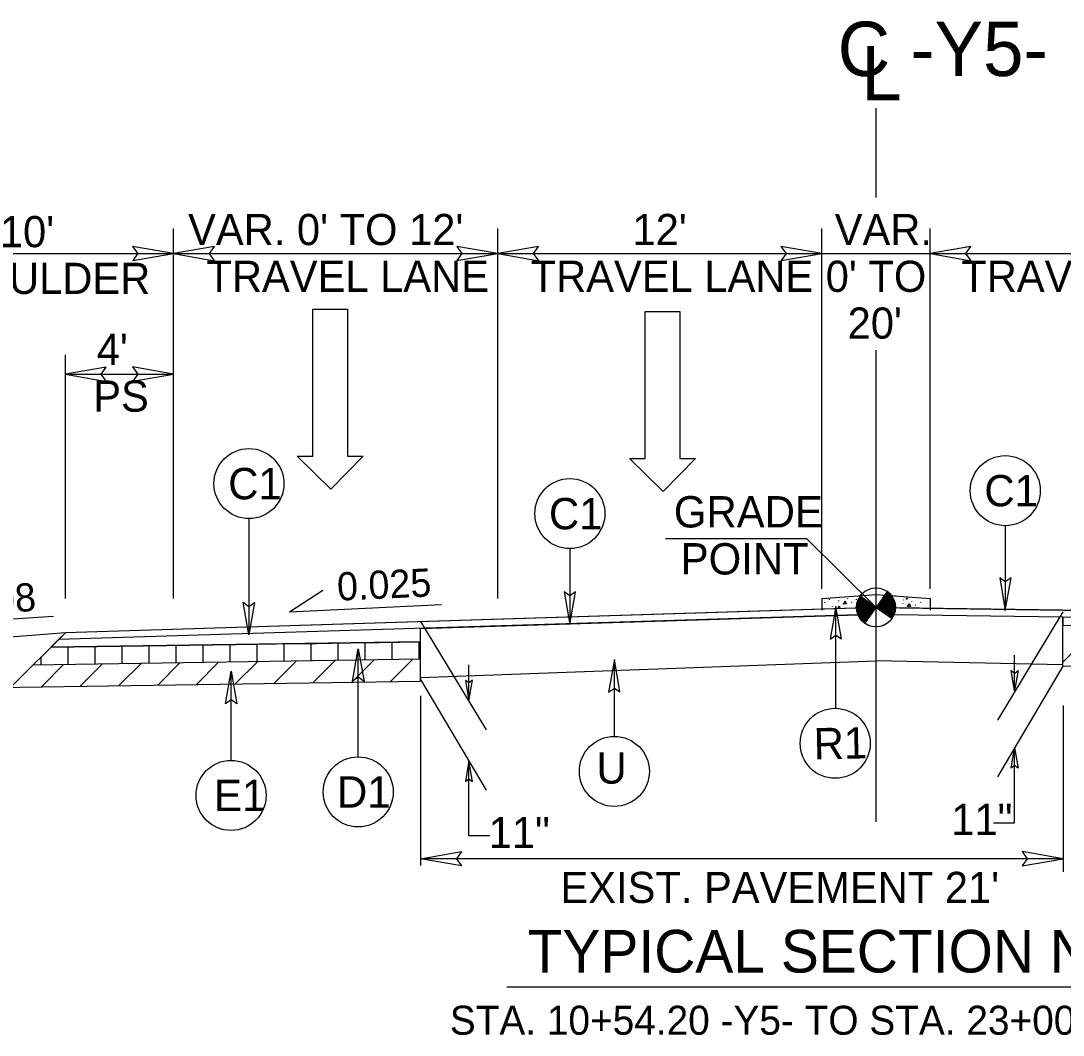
# Model space of a CAD drawing. Extents: x 2176156 to 2177167, y 76401 to 76644.
# Drawn here: x 2176264.04 to 2176302.62, y 76503.74 to 76541.28 of the extents above; entities that cross this region are included whole.
import ezdxf

# ---------------------------------------------------------------- set-up
doc = ezdxf.new("R2010")
doc.units = 0
for name, color, linetype in [('Exist Building', 7, 'Continuous'), ('Exist Building Metal Canopy', 7, 'Continuous'), ('Exist Roads Change in Surface', 7, 'Continuous'), ('Exist Roads Curbs', 7, 'Continuous'), ('Exist Roads EOP Other', 7, 'Continuous'), ('Exist Roads Soil', 7, 'Continuous'), ('Exist Structure Minor Culvert Topo', 7, 'Continuous'), ('Exist Structure Minor Drop Inlet', 7, 'Continuous'), ('Exist Utilities Other Pole CELL', 7, 'Continuous'), ('Exist Vegetation Woods Line', 7, 'Continuous'), ('Model Boundary Lines Text', 7, 'Continuous'), ('Old_Level_1', 7, 'Continuous'), ('Old_Level_3', 7, 'Continuous'), ('Prop North Arrow NAD83 for Plan Sheets CELL', 7, 'Continuous'), ('Sheet Plan CELL', 7, 'Continuous')]:
    doc.layers.add(name, color=color, linetype=linetype)

msp = doc.modelspace()

# ---------------------------------------------------------------- linework, layer by layer
at = {"layer": 'Exist Building'}
for p, q in [((2176302.609, 76517.393), (2176302.609, 76519.216)), ((2176278.832, 76516.842), (2176278.832, 76518.793)), ((2176342.792, 76516.795), (2176302.609, 76517.393)), ((2176249.154, 76516.4), (2176278.832, 76516.842))]:
    msp.add_line(p, q, dxfattribs=at)
at = {"layer": 'Exist Roads Change in Surface'}
for p, q in [((2176294.327, 76519.95), (2176294.335, 76519.938)), ((2176294.625, 76519.895), (2176294.634, 76519.881)), ((2176295.689, 76519.569), (2176295.097, 76519.98)), ((2176296.101, 76520.16), (2176295.689, 76519.569)), ((2176296.404, 76519.988), (2176296.406, 76519.998)), ((2176296.425, 76519.997), (2176296.406, 76519.988)), ((2176293.783, 76519.754), (2176293.792, 76519.774)), ((2176293.963, 76519.851), (2176293.972, 76519.871)), ((2176294.061, 76519.612), (2176294.07, 76519.598)), ((2176294.309, 76519.805), (2176294.318, 76519.825)), ((2176294.783, 76519.754), (2176294.792, 76519.774)), ((2176294.963, 76519.851), (2176294.972, 76519.871)), ((2176295.277, 76518.977), (2176295.689, 76519.569)), ((2176296.282, 76519.158), (2176295.689, 76519.569)), ((2176295.689, 76519.569), (2176296.282, 76519.158)), ((2176296.682, 76519.707), (2176296.691, 76519.727)), ((2176296.699, 76519.853), (2176296.708, 76519.84)), ((2176296.998, 76519.796), (2176297.007, 76519.783)), ((2176297.156, 76519.656), (2176297.165, 76519.676)), ((2176297.336, 76519.753), (2176297.345, 76519.773)), ((2176297.682, 76519.707), (2176297.689, 76519.722))]:
    msp.add_line(p, q, dxfattribs=at)
for points in [[(2176295.036, 76519.875), (2176295.619, 76519.469)], [(2176295.043, 76519.888), (2176295.628, 76519.48)], [(2176295.049, 76519.9), (2176295.636, 76519.492)], [(2176295.056, 76519.913), (2176295.644, 76519.504)], [(2176295.063, 76519.926), (2176295.652, 76519.516)], [(2176295.07, 76519.939), (2176295.661, 76519.528)], [(2176295.078, 76519.95), (2176295.669, 76519.54)], [(2176295.085, 76519.963), (2176295.677, 76519.551)], [(2176295.094, 76519.975), (2176295.094, 76519.975), (2176295.685, 76519.563)], [(2176295.901, 76519.874), (2176296.409, 76519.52)], [(2176295.91, 76519.885), (2176296.409, 76519.538)], [(2176295.918, 76519.897), (2176296.409, 76519.555)], [(2176295.926, 76519.909), (2176296.41, 76519.572)], [(2176295.934, 76519.921), (2176296.41, 76519.59)], [(2176295.942, 76519.933), (2176296.409, 76519.608)], [(2176295.951, 76519.945), (2176296.408, 76519.626)], [(2176295.959, 76519.956), (2176296.406, 76519.645)], [(2176295.967, 76519.968), (2176296.404, 76519.665)], [(2176295.975, 76519.98), (2176296.401, 76519.684)], [(2176295.984, 76519.992), (2176296.398, 76519.704)], [(2176295.992, 76520.004), (2176296.393, 76519.725)], [(2176296, 76520.016), (2176296.388, 76519.746)], [(2176296.008, 76520.027), (2176296.382, 76519.768)], [(2176296.017, 76520.039), (2176296.375, 76519.789)], [(2176296.025, 76520.051), (2176296.368, 76519.812)], [(2176296.033, 76520.063), (2176296.359, 76519.836)], [(2176296.041, 76520.075), (2176296.349, 76519.861)], [(2176296.05, 76520.087), (2176296.336, 76519.887)], [(2176296.058, 76520.098), (2176296.322, 76519.915)], [(2176296.066, 76520.11), (2176296.305, 76519.944)], [(2176296.074, 76520.122), (2176296.286, 76519.975)], [(2176296.082, 76520.134), (2176296.259, 76520.011)], [(2176296.091, 76520.146), (2176296.225, 76520.053)], [(2176296.099, 76520.158), (2176296.163, 76520.113)], [(2176296.801, 76519.868), (2176296.828, 76519.924), (2176296.872, 76519.891), (2176296.801, 76519.868)], [(2176294.294, 76519.554), (2176294.32, 76519.61), (2176294.365, 76519.576), (2176294.294, 76519.554)], [(2176294.484, 76519.694), (2176294.543, 76519.807), (2176294.59, 76519.703), (2176294.486, 76519.694)], [(2176294.968, 76519.571), (2176295.455, 76519.232)], [(2176294.969, 76519.605), (2176295.471, 76519.256)], [(2176294.969, 76519.588), (2176295.463, 76519.244)], [(2176294.969, 76519.552), (2176295.447, 76519.22)], [(2176294.969, 76519.535), (2176295.438, 76519.208)], [(2176294.97, 76519.517), (2176295.43, 76519.196)], [(2176294.971, 76519.622), (2176295.479, 76519.268)], [(2176294.972, 76519.638), (2176295.488, 76519.279)], [(2176294.972, 76519.498), (2176295.422, 76519.185)], [(2176294.974, 76519.654), (2176295.496, 76519.291)], [(2176294.976, 76519.671), (2176295.504, 76519.303)], [(2176294.979, 76519.686), (2176295.512, 76519.315)], [(2176294.982, 76519.702), (2176295.521, 76519.327)], [(2176294.984, 76519.717), (2176295.529, 76519.338)], [(2176294.987, 76519.733), (2176295.537, 76519.35)], [(2176294.99, 76519.748), (2176295.545, 76519.362)], [(2176294.995, 76519.763), (2176295.554, 76519.374)], [(2176294.999, 76519.777), (2176295.562, 76519.386)], [(2176295.003, 76519.792), (2176295.57, 76519.398)], [(2176295.009, 76519.806), (2176295.578, 76519.41)], [(2176295.013, 76519.82), (2176295.586, 76519.421)], [(2176295.019, 76519.834), (2176295.595, 76519.433)], [(2176295.024, 76519.848), (2176295.603, 76519.445)], [(2176295.03, 76519.861), (2176295.611, 76519.457)], [(2176295.695, 76519.578), (2176296.287, 76519.166), (2176296.287, 76519.166)], [(2176295.704, 76519.59), (2176296.295, 76519.178)], [(2176295.712, 76519.601), (2176296.302, 76519.191)], [(2176295.72, 76519.613), (2176296.31, 76519.202)], [(2176295.728, 76519.625), (2176296.317, 76519.215)], [(2176295.737, 76519.637), (2176296.324, 76519.228)], [(2176295.745, 76519.649), (2176296.331, 76519.241)], [(2176295.753, 76519.661), (2176296.337, 76519.254)], [(2176295.761, 76519.672), (2176296.344, 76519.267)], [(2176295.769, 76519.684), (2176296.349, 76519.281)], [(2176295.778, 76519.696), (2176296.355, 76519.294)], [(2176295.786, 76519.708), (2176296.361, 76519.308)], [(2176295.794, 76519.72), (2176296.366, 76519.322)], [(2176295.802, 76519.732), (2176296.37, 76519.336)], [(2176295.811, 76519.743), (2176296.376, 76519.35)], [(2176295.819, 76519.755), (2176296.38, 76519.365)], [(2176295.827, 76519.767), (2176296.385, 76519.379)], [(2176295.835, 76519.779), (2176296.389, 76519.394)], [(2176295.844, 76519.791), (2176296.392, 76519.409)], [(2176295.852, 76519.803), (2176296.395, 76519.425)], [(2176295.86, 76519.814), (2176296.398, 76519.44)], [(2176295.868, 76519.826), (2176296.401, 76519.456)], [(2176295.877, 76519.838), (2176296.404, 76519.471)], [(2176295.885, 76519.85), (2176296.405, 76519.488)], [(2176295.893, 76519.862), (2176296.407, 76519.504)], [(2176296.857, 76519.596), (2176296.917, 76519.709), (2176296.963, 76519.605), (2176296.859, 76519.596)], [(2176294.974, 76519.478), (2176295.414, 76519.173)], [(2176294.977, 76519.459), (2176295.405, 76519.161)], [(2176294.98, 76519.439), (2176295.397, 76519.149)], [(2176294.984, 76519.419), (2176295.389, 76519.137)], [(2176294.989, 76519.398), (2176295.381, 76519.125)], [(2176294.995, 76519.376), (2176295.372, 76519.114)], [(2176295.001, 76519.354), (2176295.364, 76519.102)], [(2176295.009, 76519.332), (2176295.356, 76519.09)], [(2176295.018, 76519.308), (2176295.348, 76519.078)], [(2176295.028, 76519.283), (2176295.339, 76519.066)], [(2176295.039, 76519.258), (2176295.331, 76519.055)], [(2176295.052, 76519.231), (2176295.323, 76519.043)], [(2176295.069, 76519.202), (2176295.315, 76519.031)], [(2176295.088, 76519.171), (2176295.307, 76519.019)], [(2176295.113, 76519.136), (2176295.298, 76519.007)], [(2176295.145, 76519.096), (2176295.29, 76518.995)], [(2176295.198, 76519.042), (2176295.282, 76518.983)]]:
    msp.add_lwpolyline(points, dxfattribs=at)
msp.add_circle((2176295.689, 76519.569), 0.721, dxfattribs=at)
for start, end in [(145.1751, 235.1751), (325.1751, 55.1751)]:
    msp.add_arc((2176295.689, 76519.569), 0.721, start, end, dxfattribs=at)
at = {"layer": 'Exist Roads Curbs'}
for p, q in [((2176295.689, 76519.569), (2176265.689, 76518.633)), ((2176295.689, 76519.569), (2176325.689, 76519.123)), ((2176295.022, 76519.298), (2176265.429, 76518.375)), ((2176296.361, 76519.309), (2176325.944, 76518.869))]:
    msp.add_line(p, q, dxfattribs=at)
at = {"layer": 'Exist Roads EOP Other'}
for p, q in [((2176294.969, 76519.546), (2176265.689, 76518.633)), ((2176294.969, 76519.535), (2176294.969, 76519.535)), ((2176294.97, 76519.516), (2176294.97, 76519.517)), ((2176296.408, 76519.521), (2176296.409, 76519.52)), ((2176325.689, 76519.123), (2176296.41, 76519.558)), ((2176294.977, 76519.459), (2176294.977, 76519.459)), ((2176294.98, 76519.439), (2176294.98, 76519.439)), ((2176294.984, 76519.419), (2176294.984, 76519.419)), ((2176294.989, 76519.398), (2176294.989, 76519.398)), ((2176295.001, 76519.354), (2176295.001, 76519.354)), ((2176295.009, 76519.332), (2176295.009, 76519.332)), ((2176296.376, 76519.35), (2176296.376, 76519.35)), ((2176296.385, 76519.379), (2176296.385, 76519.379)), ((2176296.389, 76519.394), (2176296.389, 76519.394)), ((2176296.403, 76519.471), (2176296.404, 76519.471)), ((2176265.689, 76518.633), (2176259.654, 76518.15)), ((2176265.689, 76518.633), (2176265.429, 76518.375))]:
    msp.add_line(p, q, dxfattribs=at)
for points in [[(2176294.969, 76519.535), (2176294.969, 76519.535)], [(2176294.97, 76519.517), (2176294.97, 76519.517)], [(2176296.409, 76519.52), (2176296.408, 76519.52)], [(2176271.988, 76518.194), (2176273.502, 76518.216), (2176274.976, 76518.238), (2176275.556, 76518.247), (2176276.248, 76518.257), (2176277.303, 76518.273), (2176278.832, 76518.296), (2176278.832, 76518.793), (2176295.022, 76519.298)], [(2176294.977, 76519.459), (2176294.977, 76519.459)], [(2176294.98, 76519.439), (2176294.98, 76519.439)], [(2176294.984, 76519.419), (2176294.984, 76519.419)], [(2176294.989, 76519.398), (2176294.989, 76519.398)], [(2176295.001, 76519.354), (2176295.001, 76519.354)], [(2176295.009, 76519.332), (2176295.009, 76519.332)], [(2176296.361, 76519.309), (2176302.609, 76519.216), (2176302.609, 76518.915), (2176304.319, 76518.89), (2176305.566, 76518.871), (2176306.49, 76518.858), (2176307.341, 76518.845), (2176308.316, 76518.83), (2176308.997, 76518.82), (2176309.894, 76518.807), (2176311.28, 76518.785)], [(2176296.376, 76519.35), (2176296.376, 76519.35)], [(2176296.385, 76519.379), (2176296.385, 76519.379)], [(2176296.389, 76519.394), (2176296.388, 76519.394)], [(2176296.404, 76519.471), (2176296.403, 76519.471)], [(2176265.429, 76518.375), (2176265.145, 76518.092), (2176271.988, 76518.194)]]:
    msp.add_lwpolyline(points, dxfattribs=at)
for start, end in [(181.8477, 182.7348), (182.7606, 184.1873), (184.2222, 187.2461), (352.1906, 353.4879), (353.4879, 354.7979), (354.7979, 356.1105), (356.1239, 357.4854), (357.4854, 358.8653), (358.8653, 359.0864), (187.2461, 188.7804), (188.7962, 190.4016), (190.402, 192.0225), (192.0545, 193.7352), (193.7596, 195.5443), (195.5443, 197.354), (197.3571, 199.2632), (199.269, 202.1386), (338.7874, 342.2846), (342.2873, 344.7024), (344.7032, 345.9093), (345.9246, 349.6664), (349.6664, 350.9233), (350.9233, 352.1755)]:
    msp.add_arc((2176295.689, 76519.569), 0.721, start, end, dxfattribs=at)
at = {"layer": 'Exist Roads Soil'}
for p, q in [((2176293.689, 76519.902), (2176295.689, 76520.052)), ((2176293.689, 76519.902), (2176293.689, 76519.463)), ((2176295.689, 76520.052), (2176297.689, 76519.902)), ((2176297.689, 76519.902), (2176297.689, 76519.463)), ((2176302.609, 76518.915), (2176326.252, 76518.563)), ((2176265.689, 76518.633), (2176263.661, 76516.616)), ((2176278.832, 76518.296), (2176265.145, 76518.092)), ((2176278.832, 76517.648), (2176264.484, 76517.434))]:
    msp.add_line(p, q, dxfattribs=at)
at = {"layer": 'Exist Structure Minor Drop Inlet'}
for p, q in [((2176274.848, 76525.17), (2176274.848, 76530.602)), ((2176274.848, 76530.602), (2176276.128, 76530.602)), ((2176276.128, 76530.602), (2176276.128, 76525.17)), ((2176287.147, 76525.085), (2176287.147, 76530.517)), ((2176287.147, 76530.517), (2176288.428, 76530.517)), ((2176288.428, 76530.517), (2176288.428, 76525.085)), ((2176275.508, 76523.948), (2176274.266, 76525.17)), ((2176274.266, 76525.17), (2176274.848, 76525.17)), ((2176276.71, 76525.17), (2176275.508, 76523.948)), ((2176276.128, 76525.17), (2176276.71, 76525.17)), ((2176287.807, 76523.863), (2176286.565, 76525.085)), ((2176286.565, 76525.085), (2176287.147, 76525.085)), ((2176289.01, 76525.085), (2176287.807, 76523.863)), ((2176288.428, 76525.085), (2176289.01, 76525.085))]:
    msp.add_line(p, q, dxfattribs=at)
at = {"layer": 'Exist Utilities Other Pole CELL'}
for p, q in [((2176273.977, 76519.41), (2176275.217, 76520.205)), ((2176273.977, 76519.41), (2176279.604, 76519.672)), ((2176260.503, 76518.935), (2176265.249, 76519.249))]:
    msp.add_line(p, q, dxfattribs=at)
at = {"layer": 'Model Boundary Lines Text'}
for p, q in [((2176265.785, 76517.454), (2176265.785, 76518.101)), ((2176266.785, 76517.469), (2176266.785, 76518.116)), ((2176267.785, 76517.484), (2176267.785, 76518.131)), ((2176268.785, 76517.498), (2176268.785, 76518.146)), ((2176269.785, 76517.513), (2176269.785, 76518.161)), ((2176270.785, 76517.528), (2176270.785, 76518.176)), ((2176271.785, 76517.543), (2176271.785, 76518.191)), ((2176272.785, 76517.558), (2176272.785, 76518.206)), ((2176273.785, 76517.573), (2176273.785, 76518.22)), ((2176274.785, 76517.588), (2176274.785, 76518.235)), ((2176275.785, 76517.603), (2176275.785, 76518.25)), ((2176276.785, 76517.618), (2176276.785, 76518.265)), ((2176277.785, 76517.632), (2176277.785, 76518.28)), ((2176278.785, 76517.647), (2176278.785, 76518.295)), ((2176302.609, 76517.536), (2176303.262, 76518.19)), ((2176264.785, 76517.439), (2176264.785, 76517.734)), ((2176271.974, 76516.74), (2176272.793, 76517.558)), ((2176273.41, 76516.761), (2176274.228, 76517.579)), ((2176274.845, 76516.782), (2176275.664, 76517.601)), ((2176276.281, 76516.804), (2176277.1, 76517.622)), ((2176277.717, 76516.825), (2176278.535, 76517.644)), ((2176264.796, 76516.633), (2176265.615, 76517.451)), ((2176266.232, 76516.654), (2176267.05, 76517.473)), ((2176267.668, 76516.676), (2176268.486, 76517.494)), ((2176269.103, 76516.697), (2176269.922, 76517.515)), ((2176270.539, 76516.718), (2176271.357, 76517.537)), ((2176282.028, 76505.529), (2176309.35, 76505.529))]:
    msp.add_line(p, q, dxfattribs=at)
at = {"layer": 'Old_Level_1'}
for points in [[(2176268.179, 76532.402), (2176269.689, 76532.662), (2176268.171, 76532.93), (2176268.364, 76532.662)], [(2176271.199, 76532.922), (2176269.689, 76532.662), (2176271.207, 76532.393), (2176271.014, 76532.662)], [(2176280.179, 76532.402), (2176281.689, 76532.662), (2176280.171, 76532.93), (2176280.364, 76532.662)], [(2176283.199, 76532.922), (2176281.689, 76532.662), (2176283.207, 76532.393), (2176283.014, 76532.662)], [(2176292.179, 76532.402), (2176293.689, 76532.662), (2176292.171, 76532.93), (2176292.364, 76532.662)], [(2176299.199, 76532.922), (2176297.689, 76532.662), (2176299.207, 76532.393), (2176299.014, 76532.662)], [(2176267.199, 76528.461), (2176265.689, 76528.201), (2176267.207, 76527.933), (2176267.014, 76528.201)], [(2176268.179, 76527.941), (2176269.689, 76528.201), (2176268.171, 76528.47), (2176268.364, 76528.201)], [(2176300.953, 76517.231), (2176300.821, 76516.476), (2176300.689, 76517.236), (2176300.823, 76517.139)], [(2176280.488, 76516.865), (2176280.62, 76516.11), (2176280.752, 76516.87), (2176280.618, 76516.773)], [(2176300.688, 76513.62), (2176300.82, 76514.375), (2176300.952, 76513.615), (2176300.818, 76513.712)], [(2176280.752, 76513.131), (2176280.62, 76513.886), (2176280.488, 76513.126), (2176280.622, 76513.223)], [(2176280.341, 76510.009), (2176278.832, 76510.269), (2176280.35, 76510.538), (2176280.157, 76510.269)], [(2176301.102, 76510.009), (2176302.611, 76510.269), (2176301.093, 76510.538), (2176301.286, 76510.269)]]:
    msp.add_lwpolyline(points, close=True, dxfattribs=at)
at = {"layer": 'Old_Level_3'}
for p, q in [((2176295.689, 76534.74), (2176295.689, 76538.044)), ((2176269.689, 76519.902), (2176269.689, 76533.589)), ((2176281.689, 76519.902), (2176281.689, 76533.589)), ((2176293.689, 76520.261), (2176293.689, 76533.589)), ((2176297.689, 76520.261), (2176297.689, 76533.589)), ((2176231.689, 76532.662), (2176295.689, 76532.662)), ((2176295.689, 76532.662), (2176359.676, 76532.662)), ((2176265.689, 76519.902), (2176265.689, 76528.911)), ((2176295.689, 76511.63), (2176295.689, 76529.086)), ((2176265.689, 76528.201), (2176269.689, 76528.201)), ((2176302.609, 76519.409), (2176300.184, 76515.401)), ((2176278.832, 76519.043), (2176281.257, 76515.035)), ((2176300.821, 76516.476), (2176300.821, 76517.804)), ((2176280.62, 76516.11), (2176280.62, 76517.438)), ((2176302.609, 76517.394), (2176300.183, 76513.299)), ((2176278.832, 76516.905), (2176281.257, 76512.81)), ((2176278.832, 76516.297), (2176278.832, 76510.016)), ((2176302.611, 76515.942), (2176302.611, 76509.778)), ((2176300.82, 76511.599), (2176300.82, 76514.375)), ((2176280.62, 76511.11), (2176280.62, 76513.886)), ((2176300.04, 76511.599), (2176300.82, 76511.599)), ((2176281.4, 76511.11), (2176280.62, 76511.11)), ((2176302.611, 76510.269), (2176278.832, 76510.269))]:
    msp.add_line(p, q, dxfattribs=at)
at = {"layer": 'Prop North Arrow NAD83 for Plan Sheets CELL'}
for p, q in [((2176272.479, 76522.854), (2176272.479, 76518.551)), ((2176300.474, 76522.593), (2176300.474, 76519.46)), ((2176287.897, 76522.122), (2176293.116, 76522.122)), ((2176293.116, 76522.122), (2176295.689, 76519.569)), ((2176284.357, 76521.743), (2176284.357, 76518.939)), ((2176294.205, 76515.834), (2176294.205, 76519.6)), ((2176276.523, 76514.036), (2176276.523, 76518.036)), ((2176286.004, 76514.796), (2176286.004, 76517.638)), ((2176271.816, 76513.907), (2176271.816, 76517.203))]:
    msp.add_line(p, q, dxfattribs=at)
for points in [[(2176300.267, 76520.66), (2176300.474, 76519.46), (2176300.687, 76520.667), (2176300.474, 76520.514)], [(2176284.151, 76520.139), (2176284.357, 76518.939), (2176284.571, 76520.146), (2176284.357, 76519.992)], [(2176272.686, 76519.751), (2176272.479, 76518.551), (2176272.266, 76519.757), (2176272.479, 76519.604)], [(2176294.412, 76518.4), (2176294.205, 76519.6), (2176293.992, 76518.393), (2176294.205, 76518.546)], [(2176276.317, 76516.836), (2176276.523, 76518.036), (2176276.737, 76516.829), (2176276.523, 76516.983)], [(2176286.21, 76516.438), (2176286.004, 76517.638), (2176285.79, 76516.431), (2176286.004, 76516.585)], [(2176271.609, 76516.003), (2176271.816, 76517.203), (2176272.029, 76515.996), (2176271.816, 76516.149)]]:
    msp.add_lwpolyline(points, close=True, dxfattribs=at)
for centre in [(2176272.479, 76524.15), (2176300.474, 76523.889), (2176284.357, 76523.039), (2176294.178, 76514.539), (2176286.004, 76513.5), (2176271.816, 76512.611), (2176276.523, 76512.74)]:
    msp.add_circle(centre, 1.296, dxfattribs=at)
at = {"layer": 'Sheet Plan CELL'}
for p in [(2176278.832, 76516.978), (2176302.609, 76517.445)]:
    msp.add_line(p, (2176295.689, 76517.588), dxfattribs=at)

# ---------------------------------------------------------------- texts
at = {"layer": 'Exist Building Metal Canopy'}
msp.add_text('TYPICAL SECTION NO.  7', height=1.5766, rotation=0, dxfattribs=at).set_placement((2176282.793, 76506.057))
at = {"layer": 'Exist Structure Minor Culvert Topo'}
for s, height, p in [("VAR. 0' TO 12'", 1.15334, (2176270.226, 76532.977)), ("12'", 1.1533, (2176286.675, 76532.977)), ("10' ", 1.1533, (2176263.259, 76532.899)), ('VAR. ', 1.1533, (2176294.16, 76532.975)), ('SHOULDER', 1.1533, (2176260.257, 76531.169)), ('TRAVEL LANE', 1.15334, (2176270.906, 76531.247)), ('TRAVEL LANE', 1.15334, (2176282.906, 76531.247)), ("0' TO ", 1.1533, (2176293.827, 76531.245)), ('TRAVEL LANE', 1.15334, (2176298.846, 76531.247)), ("20'", 1.1533, (2176294.638, 76529.515)), ("4' ", 1.1533, (2176266.845, 76528.543)), ('PS', 1.1533, (2176266.715, 76526.813)), ("EXIST. PAVEMENT 21'", 1.15334, (2176284.009, 76508.629))]:
    msp.add_text(s, height=height, dxfattribs=at).set_placement(p)
at = {"layer": 'Exist Utilities Other Pole CELL'}
for s, rotation, p in [('0.025', 2.6676, (2176275.763, 76519.815)), ('0.08', 3.7801, (2176261.913, 76519.265))]:
    msp.add_text(s, height=1.0429, rotation=rotation, dxfattribs=at).set_placement(p)
at = {"layer": 'Exist Vegetation Woods Line'}
for s, height, p in [('C -Y5- ', 2.0131, (2176294.268, 76539.233)), ('STA. 10+54.20 -Y5- TO STA. 23+00.00 -Y5-', 1.0742, (2176279.913, 76503.754))]:
    msp.add_text(s, height=height, dxfattribs=at).set_placement(p)
msp.add_text('L', height=2.013, rotation=359.9469, dxfattribs=at).set_placement((2176295.146, 76538.331))
at = {"layer": 'Prop North Arrow NAD83 for Plan Sheets CELL'}
for s, rotation, p in [('C1', 0.0003, (2176271.71, 76523.57)), ('C1', 359.9997, (2176299.699, 76523.309)), ('C1', 359.9997, (2176283.583, 76522.459)), ('GRADE', 359.9998, (2176288.206, 76522.527)), ('POINT', 359.9998, (2176288.459, 76520.787)), ('R1', 1.1751, (2176293.393, 76513.942)), ('U', 359.9997, (2176285.34, 76513.046)), ('D1', 0.0003, (2176275.738, 76512.16)), ('E1', 0.0003, (2176271.187, 76512.031))]:
    msp.add_text(s, height=1.16, rotation=rotation, dxfattribs=at).set_placement(p)
for p in [(2176298.475, 76511.149), (2176281.352, 76510.66)]:
    msp.add_text('11"', height=1.1533, dxfattribs=at).set_placement(p)

doc.saveas('drawing.dxf')
